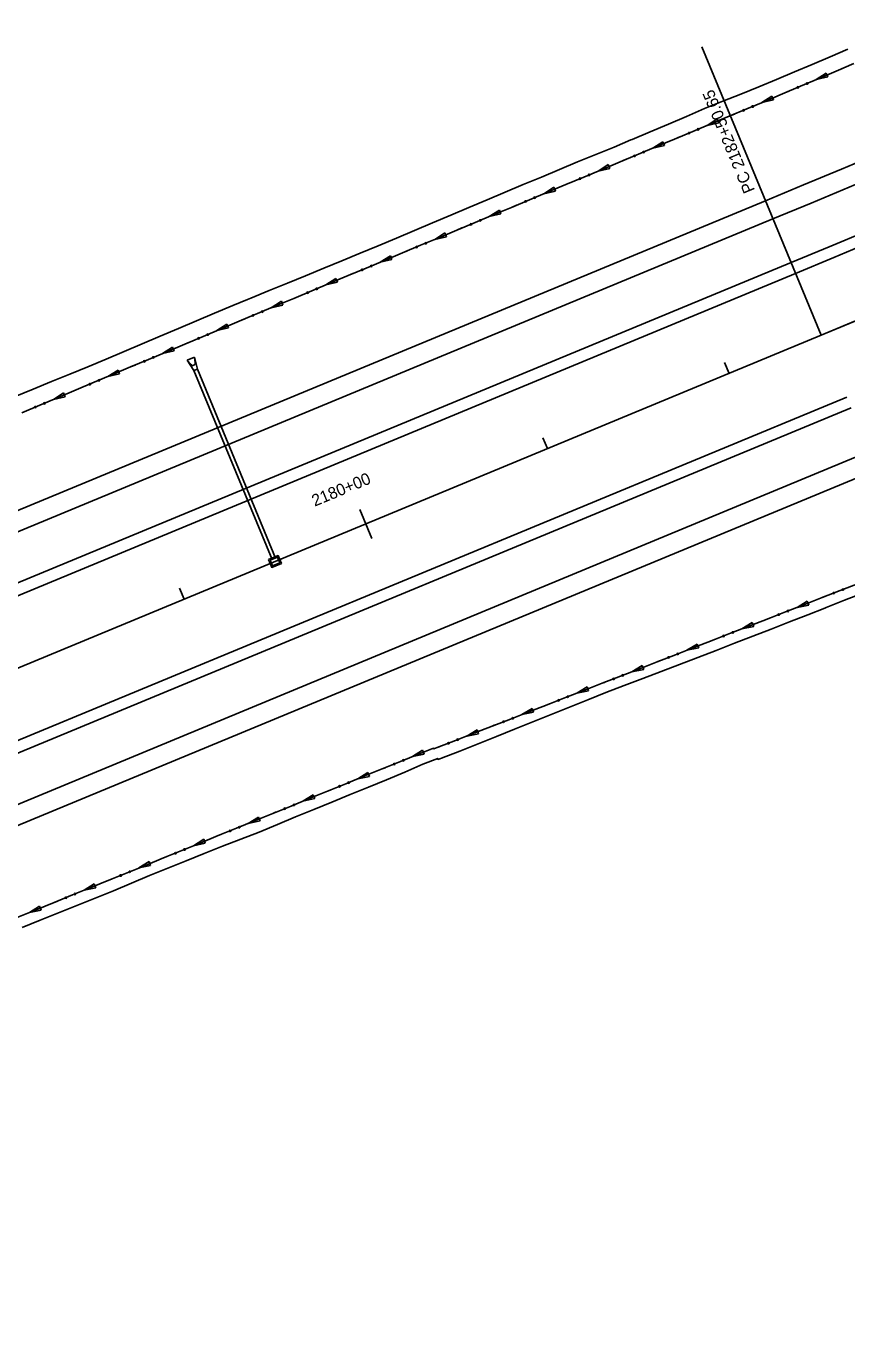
# Model space of a CAD drawing. Extents: x 1611108 to 1749517, y 619561 to 797725.
# Drawn here: x 1723456 to 1723874, y 768515 to 769183 of the extents above; entities that cross this region are included whole.
import ezdxf

# ---------------------------------------------------------------- set-up
doc = ezdxf.new("R2010")
doc.units = 0
for name, color, linetype in [('R_Ditch', 7, 'Continuous'), ('R_Drainage', 7, 'Continuous'), ('R_Horz Alg', 7, 'Continuous'), ('R_Horz Alg Annot', 7, 'Continuous'), ('R_Horz Alg Stationing', 7, 'Continuous'), ('R_Proposed Const Limits', 7, 'Continuous'), ('R_Proposed Road', 7, 'Continuous')]:
    doc.layers.add(name, color=color, linetype=linetype)

msp = doc.modelspace()

# ---------------------------------------------------------------- linework, layer by layer
at = {"layer": 'R_Ditch'}
for p, q in [((1723863.15, 769158.91), (1723858.05, 769155.58)), ((1723858.05, 769155.58), (1723863.98, 769156.96)), ((1723863.98, 769156.96), (1723863.15, 769158.91)), ((1723835.5, 769147.18), (1723830.39, 769143.87)), ((1723830.39, 769143.87), (1723836.33, 769145.23)), ((1723836.33, 769145.23), (1723835.5, 769147.18)), ((1723807.81, 769135.56), (1723802.68, 769132.27)), ((1723802.68, 769132.27), (1723808.63, 769133.61)), ((1723808.63, 769133.61), (1723807.81, 769135.56)), ((1723780.1, 769123.97), (1723774.97, 769120.68)), ((1723780.91, 769122.02), (1723780.1, 769123.97)), ((1723774.97, 769120.68), (1723780.91, 769122.02)), ((1723752.38, 769112.38), (1723747.26, 769109.09)), ((1723747.26, 769109.09), (1723753.2, 769110.43)), ((1723753.2, 769110.43), (1723752.38, 769112.38)), ((1723724.67, 769100.8), (1723719.54, 769097.51)), ((1723719.54, 769097.51), (1723725.49, 769098.84)), ((1723725.49, 769098.84), (1723724.67, 769100.8)), ((1723696.96, 769089.21), (1723691.83, 769085.92)), ((1723691.83, 769085.92), (1723697.77, 769087.26)), ((1723697.77, 769087.26), (1723696.96, 769089.21)), ((1723669.24, 769077.62), (1723664.12, 769074.33)), ((1723670.06, 769075.67), (1723669.24, 769077.62)), ((1723664.12, 769074.33), (1723670.06, 769075.67)), ((1723641.53, 769066.04), (1723636.4, 769062.74)), ((1723636.4, 769062.74), (1723642.35, 769064.08)), ((1723642.35, 769064.08), (1723641.53, 769066.04)), ((1723613.82, 769054.45), (1723608.69, 769051.16)), ((1723608.69, 769051.16), (1723614.63, 769052.5)), ((1723614.63, 769052.5), (1723613.82, 769054.45)), ((1723586.1, 769042.86), (1723580.98, 769039.57)), ((1723586.92, 769040.91), (1723586.1, 769042.86)), ((1723580.98, 769039.57), (1723586.92, 769040.91)), ((1723558.4, 769031.24), (1723553.29, 769027.93)), ((1723553.29, 769027.93), (1723559.23, 769029.29)), ((1723559.23, 769029.29), (1723558.4, 769031.24)), ((1723530.72, 769019.57), (1723525.6, 769016.27)), ((1723525.6, 769016.27), (1723531.54, 769017.62)), ((1723531.54, 769017.62), (1723530.72, 769019.57)), ((1723503.04, 769007.91), (1723497.92, 769004.61)), ((1723497.92, 769004.61), (1723503.86, 769005.96)), ((1723503.86, 769005.96), (1723503.04, 769007.91)), ((1723475.36, 768996.25), (1723470.24, 768992.95)), ((1723476.18, 768994.3), (1723475.36, 768996.25)), ((1723470.24, 768992.95), (1723476.18, 768994.3)), ((1723853.56, 768890.38), (1723848.35, 768887.21)), ((1723854.33, 768888.41), (1723853.56, 768890.38)), ((1723848.35, 768887.21), (1723854.33, 768888.41)), ((1723825.57, 768879.47), (1723820.36, 768876.31)), ((1723820.36, 768876.31), (1723826.34, 768877.5)), ((1723826.34, 768877.5), (1723825.57, 768879.47)), ((1723797.58, 768868.57), (1723792.37, 768865.4)), ((1723792.37, 768865.4), (1723798.35, 768866.6)), ((1723798.35, 768866.6), (1723797.58, 768868.57)), ((1723769.59, 768857.66), (1723764.39, 768854.5)), ((1723764.39, 768854.5), (1723770.36, 768855.69)), ((1723770.36, 768855.69), (1723769.59, 768857.66)), ((1723741.6, 768846.76), (1723736.4, 768843.59)), ((1723736.4, 768843.59), (1723742.37, 768844.78)), ((1723742.37, 768844.78), (1723741.6, 768846.76)), ((1723713.61, 768835.85), (1723708.41, 768832.69)), ((1723714.38, 768833.88), (1723713.61, 768835.85)), ((1723708.41, 768832.69), (1723714.38, 768833.88)), ((1723685.63, 768824.95), (1723680.42, 768821.78)), ((1723680.42, 768821.78), (1723686.39, 768822.97)), ((1723686.39, 768822.97), (1723685.63, 768824.95)), ((1723657.91, 768814.57), (1723652.75, 768811.33)), ((1723652.75, 768811.33), (1723658.71, 768812.61)), ((1723658.71, 768812.61), (1723657.91, 768814.57)), ((1723630.09, 768803.24), (1723624.93, 768800)), ((1723630.89, 768801.28), (1723630.09, 768803.24)), ((1723624.93, 768800), (1723630.89, 768801.28)), ((1723602.27, 768791.91), (1723597.11, 768788.67)), ((1723597.11, 768788.67), (1723603.07, 768789.95)), ((1723603.07, 768789.95), (1723602.27, 768791.91)), ((1723574.45, 768780.59), (1723569.29, 768777.34)), ((1723569.29, 768777.34), (1723575.25, 768778.63)), ((1723575.25, 768778.63), (1723574.45, 768780.59)), ((1723546.63, 768769.26), (1723541.47, 768766.01)), ((1723547.43, 768767.3), (1723546.63, 768769.26)), ((1723541.47, 768766.01), (1723547.43, 768767.3)), ((1723518.81, 768757.93), (1723513.65, 768754.69)), ((1723513.65, 768754.69), (1723519.61, 768755.97)), ((1723519.61, 768755.97), (1723518.81, 768757.93)), ((1723490.99, 768746.6), (1723485.83, 768743.36)), ((1723485.83, 768743.36), (1723491.79, 768744.64)), ((1723491.79, 768744.64), (1723490.99, 768746.6)), ((1723463.17, 768735.27), (1723458.01, 768732.03)), ((1723458.01, 768732.03), (1723463.97, 768733.31)), ((1723463.97, 768733.31), (1723463.17, 768735.27))]:
    msp.add_line(p, q, dxfattribs=at)
for points in [[(1723877.24, 769163.78), (1723868.2, 769159.91), (1723859.14, 769156.05), (1723850.08, 769152.2), (1723841.02, 769148.36), (1723831.96, 769144.53), (1723822.88, 769140.72), (1723813.79, 769136.91), (1723804.57, 769133.06), (1723795.34, 769129.2), (1723786.12, 769125.34), (1723776.89, 769121.48), (1723767.66, 769117.63), (1723766.95, 769117.33), (1723758.44, 769113.77), (1723749.21, 769109.91), (1723739.99, 769106.05), (1723730.76, 769102.2), (1723721.53, 769098.34), (1723712.31, 769094.48), (1723703.08, 769090.62), (1723693.86, 769086.77), (1723684.63, 769082.91), (1723675.4, 769079.05), (1723666.18, 769075.19), (1723656.95, 769071.34), (1723647.73, 769067.48), (1723638.5, 769063.62), (1723629.27, 769059.76), (1723620.05, 769055.91), (1723610.82, 769052.05), (1723601.59, 769048.19), (1723592.37, 769044.33), (1723583.14, 769040.47), (1723573.92, 769036.62), (1723572.21, 769035.9), (1723572.2, 769035.9), (1723564.7, 769032.74), (1723555.48, 769028.86), (1723546.27, 769024.97), (1723537.05, 769021.09), (1723527.84, 769017.21), (1723518.62, 769013.33), (1723509.4, 769009.45), (1723500.19, 769005.56), (1723490.97, 769001.68), (1723481.76, 768997.8), (1723472.54, 768993.92), (1723463.32, 768990.04), (1723454.11, 768986.15)], [(1723871.85, 769161.47), (1723868.2, 769159.91), (1723859.14, 769156.05), (1723858.05, 769155.58)], [(1723871.88, 769161.49), (1723871.85, 769161.47)], [(1723844.21, 769149.71), (1723841.02, 769148.36), (1723831.96, 769144.53), (1723830.39, 769143.87)], [(1723844.24, 769149.72), (1723844.21, 769149.71)], [(1723816.52, 769138.06), (1723813.79, 769136.91), (1723804.57, 769133.06), (1723802.68, 769132.27)], [(1723816.56, 769138.07), (1723816.52, 769138.06)], [(1723788.81, 769126.47), (1723786.12, 769125.34), (1723776.89, 769121.48), (1723774.97, 769120.68)], [(1723788.84, 769126.48), (1723788.81, 769126.47)], [(1723761.1, 769114.88), (1723758.44, 769113.77), (1723749.21, 769109.91), (1723747.26, 769109.09)], [(1723761.13, 769114.89), (1723761.1, 769114.88)], [(1723733.38, 769103.29), (1723730.76, 769102.2), (1723721.53, 769098.34), (1723719.54, 769097.51)], [(1723733.42, 769103.31), (1723733.38, 769103.29)], [(1723705.67, 769091.7), (1723703.08, 769090.62), (1723693.86, 769086.77), (1723691.83, 769085.92)], [(1723705.7, 769091.72), (1723705.67, 769091.71)], [(1723677.96, 769080.12), (1723675.4, 769079.05), (1723666.18, 769075.19), (1723664.12, 769074.33)], [(1723677.99, 769080.13), (1723677.96, 769080.12)], [(1723650.24, 769068.53), (1723647.73, 769067.48), (1723638.5, 769063.62), (1723636.4, 769062.74)], [(1723650.28, 769068.55), (1723650.24, 769068.53)], [(1723622.53, 769056.94), (1723620.05, 769055.91), (1723610.82, 769052.05), (1723608.69, 769051.16)], [(1723622.56, 769056.96), (1723622.53, 769056.94)], [(1723594.82, 769045.36), (1723592.37, 769044.33), (1723583.14, 769040.47), (1723580.98, 769039.57)], [(1723594.85, 769045.37), (1723594.82, 769045.36)], [(1723567.11, 769033.76), (1723564.7, 769032.74), (1723555.48, 769028.86), (1723553.29, 769027.93)], [(1723567.14, 769033.77), (1723567.11, 769033.76)], [(1723539.43, 769022.09), (1723537.05, 769021.09), (1723527.84, 769017.21), (1723525.6, 769016.27)], [(1723539.46, 769022.11), (1723539.43, 769022.09)], [(1723511.75, 769010.43), (1723509.4, 769009.45), (1723500.19, 769005.56), (1723497.92, 769004.61)], [(1723511.78, 769010.45), (1723511.75, 769010.43)], [(1723484.06, 768998.77), (1723481.76, 768997.8), (1723472.54, 768993.92), (1723470.24, 768992.95)], [(1723484.1, 768998.79), (1723484.06, 768998.77)], [(1723456.42, 768987.12), (1723456.38, 768987.11)], [(1723452.12, 768729.63), (1723461.39, 768733.4), (1723470.65, 768737.18), (1723479.91, 768740.95), (1723489.17, 768744.72), (1723498.43, 768748.49), (1723507.7, 768752.26), (1723516.96, 768756.03), (1723526.22, 768759.8), (1723535.48, 768763.57), (1723544.74, 768767.35), (1723554, 768771.12), (1723563.27, 768774.89), (1723572.53, 768778.66), (1723581.79, 768782.43), (1723591.05, 768786.2), (1723600.31, 768789.97), (1723609.57, 768793.75), (1723618.84, 768797.52), (1723628.1, 768801.29), (1723637.36, 768805.06), (1723646.62, 768808.83), (1723655.88, 768812.6), (1723663.42, 768815.67), (1723663.61, 768815.23), (1723665.34, 768815.91), (1723674.66, 768819.54), (1723683.98, 768823.17), (1723693.3, 768826.8), (1723702.62, 768830.43), (1723711.94, 768834.06), (1723721.26, 768837.69), (1723730.58, 768841.33), (1723739.9, 768844.96), (1723749.22, 768848.59), (1723758.54, 768852.22), (1723767.86, 768855.85), (1723777.18, 768859.48), (1723786.5, 768863.11), (1723795.82, 768866.74), (1723805.14, 768870.38), (1723814.46, 768874.01), (1723823.78, 768877.64), (1723833.09, 768881.27), (1723842.41, 768884.9), (1723851.73, 768888.53), (1723860.33, 768891.88), (1723861.05, 768892.16), (1723870.37, 768895.8), (1723879.69, 768899.43)], [(1723862.33, 768892.66), (1723861.05, 768892.16), (1723860.33, 768891.88), (1723851.73, 768888.53), (1723848.35, 768887.21)], [(1723862.36, 768892.67), (1723862.33, 768892.66)], [(1723834.34, 768881.75), (1723833.09, 768881.27), (1723823.78, 768877.64), (1723820.36, 768876.31)], [(1723834.37, 768881.77), (1723834.34, 768881.75)], [(1723806.35, 768870.85), (1723805.14, 768870.38), (1723795.82, 768866.74), (1723792.37, 768865.4)], [(1723806.39, 768870.86), (1723806.35, 768870.85)], [(1723778.36, 768859.94), (1723777.18, 768859.48), (1723767.86, 768855.85), (1723764.39, 768854.5)], [(1723778.4, 768859.96), (1723778.36, 768859.94)], [(1723750.37, 768849.04), (1723749.22, 768848.59), (1723739.9, 768844.96), (1723736.4, 768843.59)], [(1723750.41, 768849.05), (1723750.37, 768849.04)], [(1723722.39, 768838.13), (1723721.26, 768837.69), (1723711.94, 768834.06), (1723708.41, 768832.69)], [(1723722.42, 768838.15), (1723722.39, 768838.13)], [(1723694.4, 768827.23), (1723693.3, 768826.8), (1723683.98, 768823.17), (1723680.42, 768821.78)], [(1723694.43, 768827.24), (1723694.4, 768827.23)], [(1723666.41, 768816.32), (1723665.34, 768815.91), (1723663.61, 768815.23), (1723663.42, 768815.67), (1723655.88, 768812.6), (1723652.75, 768811.33)], [(1723666.44, 768816.34), (1723666.41, 768816.32)], [(1723638.82, 768805.66), (1723637.36, 768805.06), (1723628.1, 768801.29), (1723624.93, 768800)], [(1723638.86, 768805.67), (1723638.82, 768805.66)], [(1723611, 768794.33), (1723609.57, 768793.75), (1723600.31, 768789.97), (1723597.11, 768788.67)], [(1723611.04, 768794.34), (1723611, 768794.33)], [(1723583.18, 768783), (1723581.79, 768782.43), (1723572.53, 768778.66), (1723569.29, 768777.34)], [(1723583.22, 768783.01), (1723583.18, 768783)], [(1723555.36, 768771.67), (1723554, 768771.12), (1723544.74, 768767.35), (1723541.47, 768766.01)], [(1723555.4, 768771.69), (1723555.36, 768771.67)], [(1723527.54, 768760.34), (1723526.22, 768759.8), (1723516.96, 768756.03), (1723513.65, 768754.69)], [(1723527.58, 768760.36), (1723527.54, 768760.34)], [(1723499.72, 768749.01), (1723498.43, 768748.49), (1723489.17, 768744.72), (1723485.83, 768743.36)], [(1723499.76, 768749.03), (1723499.72, 768749.01)], [(1723471.9, 768737.69), (1723470.65, 768737.18), (1723461.39, 768733.4), (1723458.01, 768732.03)], [(1723471.94, 768737.7), (1723471.9, 768737.69)]]:
    msp.add_lwpolyline(points, dxfattribs=at)
for centre in [(1723848.85, 769151.63), (1723853.46, 769153.59), (1723821.17, 769139.96), (1723825.79, 769141.9), (1723798.08, 769130.3), (1723793.46, 769128.37), (1723765.74, 769116.78), (1723770.36, 769118.72), (1723738.03, 769105.2), (1723742.65, 769107.13), (1723710.32, 769093.61), (1723714.94, 769095.54), (1723687.23, 769083.95), (1723682.6, 769082.02), (1723654.89, 769070.43), (1723659.51, 769072.37), (1723627.18, 769058.85), (1723631.8, 769060.78), (1723604.09, 769049.19), (1723599.46, 769047.26), (1723571.75, 769035.67), (1723576.37, 769037.61), (1723544.07, 769024.01), (1723548.69, 769025.95), (1723516.39, 769012.35), (1723521, 769014.29), (1723493.32, 769002.63), (1723488.71, 769000.69), (1723461.02, 768989.03), (1723465.64, 768990.97), (1723871.69, 768896.27), (1723867.02, 768894.45), (1723839.03, 768883.54), (1723843.7, 768885.36), (1723811.04, 768872.64), (1723815.71, 768874.46), (1723787.72, 768863.55), (1723783.05, 768861.73), (1723755.07, 768850.83), (1723759.73, 768852.65), (1723727.08, 768839.92), (1723731.75, 768841.74), (1723699.09, 768829.02), (1723703.76, 768830.84), (1723671.1, 768818.11), (1723675.77, 768819.93), (1723648.13, 768809.41), (1723643.49, 768807.52), (1723615.67, 768796.19), (1723620.31, 768798.08), (1723587.85, 768784.86), (1723592.49, 768786.75), (1723564.67, 768775.42), (1723560.03, 768773.53), (1723532.21, 768762.2), (1723536.85, 768764.09), (1723504.39, 768750.87), (1723509.03, 768752.76), (1723476.57, 768739.55), (1723481.21, 768741.44)]:
    msp.add_circle(centre, 0.375, dxfattribs=at)
at = {"layer": 'R_Drainage'}
for p, q in [((1723541.98, 769014.42), (1723538.29, 769012.89)), ((1723541.55, 769007.61), (1723538.29, 769012.89)), ((1723538.29, 769012.89), (1723540.18, 769010.64)), ((1723543.4, 769008.38), (1723541.98, 769014.42)), ((1723541.98, 769014.42), (1723542.23, 769011.49)), ((1723543.4, 769008.38), (1723541.55, 769007.61)), ((1723581.35, 768911.53), (1723541.55, 769007.61)), ((1723583.2, 768912.3), (1723543.4, 769008.38))]:
    msp.add_line(p, q, dxfattribs=at)
for points in [[(1723579.56, 768911.51), (1723581.21, 768907.51), (1723586.14, 768909.55), (1723584.48, 768913.55)], [(1723580.43, 768911.15), (1723581.58, 768908.38), (1723585.27, 768909.91), (1723584.12, 768912.68)]]:
    msp.add_lwpolyline(points, close=True, dxfattribs=at)
msp.add_arc((1723541.07, 769011.38), 1.17, 220.02993, 4.97008, dxfattribs=at)
at = {"layer": 'R_Horz Alg'}
msp.add_line((1715964.86, 765755.05), (1723860.62, 769025.58), dxfattribs=at)
msp.add_arc((1720937.13, 776083.5), 7639.44, 292.5, 312.75, dxfattribs=at)
at = {"layer": 'R_Horz Alg Annot'}
for points in [[(1723860.62, 769025.58), (1725121, 769547.65)], [(1723860.62, 769025.58), (1723799.9, 769172.17)]]:
    msp.add_lwpolyline(points, dxfattribs=at)
at = {"layer": 'R_Horz Alg Stationing'}
for points in [[(1723811.52, 769011.74), (1723813.82, 769006.2)], [(1723719.14, 768973.47), (1723721.43, 768967.93)], [(1723625.98, 768937.05), (1723632.1, 768922.27)], [(1723534.36, 768896.94), (1723536.66, 768891.39)]]:
    msp.add_lwpolyline(points, dxfattribs=at)
at = {"layer": 'R_Proposed Const Limits'}
for points in [[(1723874.17, 769171.01), (1723865.13, 769167.14), (1723856.08, 769163.3), (1723847.03, 769159.47), (1723837.97, 769155.66), (1723828.9, 769151.86), (1723819.78, 769148.18), (1723810.63, 769144.55), (1723801.36, 769140.81), (1723792.15, 769136.9), (1723782.95, 769132.99), (1723773.74, 769129.09), (1723764.53, 769125.19), (1723763.82, 769124.89), (1723755.32, 769121.3), (1723746.08, 769117.47), (1723736.79, 769113.78), (1723727.55, 769109.94), (1723718.34, 769106.05), (1723709.12, 769102.17), (1723699.91, 769098.28), (1723690.7, 769094.4), (1723681.47, 769090.55), (1723672.26, 769086.64), (1723663.05, 769082.74), (1723653.84, 769078.84), (1723644.64, 769074.94), (1723635.41, 769071.08), (1723626.16, 769067.27), (1723616.92, 769063.47), (1723607.67, 769059.66), (1723598.42, 769055.86), (1723589.17, 769052.06), (1723579.91, 769048.27), (1723570.66, 769044.48), (1723568.95, 769043.78), (1723568.94, 769043.77), (1723561.42, 769040.65), (1723552.19, 769036.81), (1723542.98, 769032.92), (1723533.77, 769029.02), (1723524.56, 769025.11), (1723515.36, 769021.2), (1723506.17, 769017.24), (1723496.96, 769013.37), (1723487.72, 769009.54), (1723478.46, 769005.76), (1723469.2, 769001.99), (1723459.94, 768998.21), (1723450.71, 768994.36)], [(1723454.3, 768724.38), (1723463.53, 768728.22), (1723472.82, 768731.93), (1723482.11, 768735.63), (1723491.4, 768739.33), (1723500.69, 768743.03), (1723509.92, 768746.89), (1723519.12, 768750.8), (1723528.39, 768754.56), (1723537.65, 768758.33), (1723546.92, 768762.1), (1723556.25, 768765.7), (1723565.58, 768769.29), (1723574.89, 768772.96), (1723584.12, 768776.8), (1723593.36, 768780.64), (1723602.6, 768784.44), (1723611.86, 768788.23), (1723621.12, 768791.99), (1723630.39, 768795.75), (1723639.66, 768799.51), (1723648.87, 768803.4), (1723658.03, 768807.43), (1723665.6, 768810.41), (1723665.81, 768809.93), (1723667.55, 768810.58), (1723676.88, 768814.16), (1723686.16, 768817.89), (1723695.45, 768821.62), (1723704.73, 768825.34), (1723714.01, 768829.05), (1723723.3, 768832.76), (1723732.59, 768836.47), (1723741.89, 768840.14), (1723751.17, 768843.87), (1723760.51, 768847.45), (1723769.86, 768851.02), (1723779.2, 768854.59), (1723788.55, 768858.16), (1723797.89, 768861.74), (1723807.22, 768865.35), (1723816.55, 768868.95), (1723825.88, 768872.56), (1723835.21, 768876.17), (1723844.54, 768879.77), (1723853.84, 768883.45), (1723862.42, 768886.84), (1723863.14, 768887.12), (1723872.44, 768890.8), (1723881.74, 768894.48)]]:
    msp.add_lwpolyline(points, dxfattribs=at)
at = {"layer": 'R_Proposed Road'}
for p, q in [((1715936.54, 765823.42), (1723832.3, 769093.95)), ((1715940.37, 765814.18), (1723836.12, 769084.71)), ((1715949.55, 765792.01), (1723845.31, 769062.54)), ((1715951.85, 765786.47), (1723847.6, 769056.99)), ((1715977.87, 765723.64), (1723873.63, 768994.17)), ((1715980.17, 765718.1), (1723875.92, 768988.63)), ((1715989.35, 765695.93), (1723885.11, 768966.45)), ((1715993.18, 765686.69), (1723888.93, 768957.22))]:
    msp.add_line(p, q, dxfattribs=at)
for radius in [7565.44, 7575.44, 7599.44, 7605.44]:
    msp.add_arc((1720937.13, 776083.5), radius, 292.5, 312.75, dxfattribs=at)

# ---------------------------------------------------------------- texts
at = {"layer": 'R_Horz Alg Annot'}
msp.add_text('PC 2182+50.65', height=6, rotation=112.5, dxfattribs=at).set_placement((1723827.04, 769099.31))
at = {"layer": 'R_Horz Alg Stationing'}
msp.add_text('2180+00', height=6, rotation=22.5, dxfattribs=at).set_placement((1723603.08, 768938.39))

doc.saveas('drawing.dxf')
